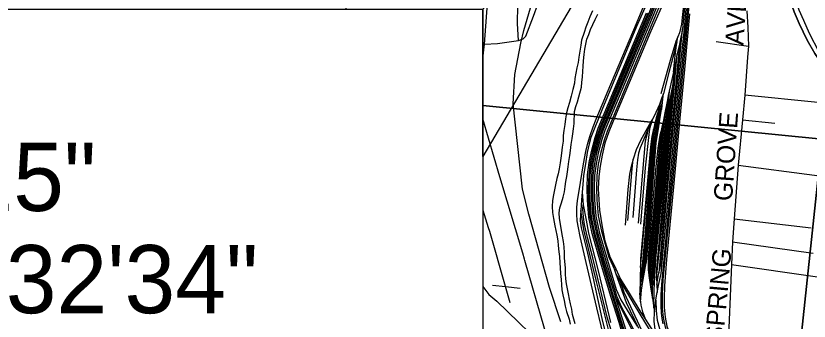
# Model space of a CAD drawing. Extents: x -8.2 to 38.5, y -0.1 to 21.9.
# Drawn here: x 4.076 to 5.706, y 16.75 to 17.376 of the extents above; entities that cross this region are included whole.
import ezdxf

# ---------------------------------------------------------------- set-up
doc = ezdxf.new("R2010")
doc.units = 0
for name, color, linetype in [('GM_X_Adjacent_County', 7, 'Continuous'), ('GM_X_Adjacent_County_Text', 7, 'Continuous'), ('GM_X_Airport_Location_Class_3', 7, 'Continuous'), ('GM_X_Major_Lake', 7, 'Continuous'), ('GM_X_Minor_River', 7, 'Continuous'), ('GM_X_State_Location', 7, 'Continuous'), ('GM_X_Township_Subdivision_Text', 7, 'Continuous'), ('GM_X_Township_Text', 7, 'Continuous'), ('GM_X_US_Location', 7, 'Continuous')]:
    doc.layers.add(name, color=color, linetype=linetype)

msp = doc.modelspace()

# ---------------------------------------------------------------- linework, layer by layer
at = {"layer": 'GM_X_Adjacent_County'}
for points in [[(5.0356, 17.3899), (5.4813, 17.8434), (5.0356, 17.0876)], [(2.2499, 17.3899), (5.0356, 17.3899), (5.0356, 16.67), (2.2499, 16.67)]]:
    msp.add_lwpolyline(points, close=True, dxfattribs=at)
at = {"layer": 'GM_X_Adjacent_County_Text'}
for points in [[(4.7544, 17.3899), (4.8395, 18.1926), (5.838, 18.0925), (5.7325, 17.1233), (5.0356, 17.1922)], [(5.0356, 17.1922), (5.7325, 17.1233), (5.6225, 16.0867), (4.6267, 16.1928), (4.6777, 16.67)]]:
    msp.add_lwpolyline(points, dxfattribs=at)
msp.add_lwpolyline([(5.7325, 17.1233), (6.7536, 16.9855), (6.65, 15.9814), (5.6225, 16.0867)], close=True, dxfattribs=at)
at = {"layer": 'GM_X_Airport_Location_Class_3'}
msp.add_lwpolyline([(5.6577, 17.4416), (5.6636, 17.4182), (5.675, 17.3847), (5.6851, 17.361), (5.7015, 17.3269), (5.7176, 17.2991), (5.74, 17.266), (5.7809, 17.2092), (5.8048, 17.1752), (5.8251, 17.1446), (5.8393, 17.1188), (5.8519, 17.0921), (5.8616, 17.0684)], dxfattribs=at)
at = {"layer": 'GM_X_Minor_River'}
for points in [[(5.2604, 17.3869), (5.2555, 17.3745), (5.2511, 17.3636), (5.247, 17.3534), (5.2433, 17.3425), (5.2383, 17.3267), (5.2365, 17.3161), (5.2346, 17.304), (5.2324, 17.2916), (5.2309, 17.2806), (5.2287, 17.27), (5.2265, 17.2587), (5.2247, 17.2481), (5.2236, 17.2383), (5.2202, 17.2251), (5.2168, 17.2115), (5.2131, 17.1987), (5.2101, 17.1877), (5.2075, 17.1772), (5.2053, 17.1651), (5.2038, 17.1537), (5.2016, 17.1409), (5.2005, 17.1307), (5.2002, 17.1189), (5.1987, 17.1068), (5.1969, 17.0943), (5.1954, 17.0845), (5.194, 17.0747), (5.1922, 17.0622), (5.19, 17.0524), (5.1874, 17.0426), (5.1848, 17.0297), (5.1826, 17.0195), (5.1804, 17.009), (5.1786, 16.9976), (5.1779, 16.9851), (5.1787, 16.9726), (5.1806, 16.9604), (5.1836, 16.9451), (5.1852, 16.9355), (5.1876, 16.926)], [(5.2033, 16.8899), (5.2025, 16.9024), (5.2009, 16.9131), (5.1989, 16.9238), (5.197, 16.936), (5.1947, 16.949), (5.1927, 16.9604), (5.1919, 16.9722), (5.1933, 16.982), (5.197, 16.9926), (5.2004, 17.0039), (5.203, 17.0148), (5.2048, 17.0261), (5.2062, 17.0363), (5.208, 17.0466), (5.2091, 17.0564), (5.2109, 17.0666), (5.2123, 17.0776), (5.2138, 17.0897), (5.2152, 17.1003), (5.2171, 17.1124), (5.2186, 17.1245), (5.22, 17.1343), (5.2214, 17.1445), (5.2232, 17.1555), (5.2239, 17.1798), (5.2265, 17.19), (5.2298, 17.1997), (5.2327, 17.2103), (5.2378, 17.2299), (5.2389, 17.2401), (5.2399, 17.2507), (5.241, 17.2628), (5.2413, 17.2727), (5.2424, 17.2841), (5.2439, 17.2969), (5.245, 17.3083), (5.2468, 17.3185), (5.2493, 17.3283), (5.253, 17.3381), (5.2567, 17.3482), (5.2612, 17.3587), (5.266, 17.3689), (5.2716, 17.3801)], [(5.1876, 16.926), (5.1895, 16.9145), (5.1904, 16.9046), (5.1916, 16.8921), (5.1928, 16.8826), (5.1936, 16.8696), (5.1944, 16.8593), (5.1949, 16.8476), (5.196, 16.8354), (5.1969, 16.8243), (5.1977, 16.8141), (5.1997, 16.8038), (5.2024, 16.7919), (5.2047, 16.7801), (5.2075, 16.7694), (5.2127, 16.7533), (5.215, 16.7431)], [(5.2249, 16.7442), (5.2222, 16.7538), (5.2198, 16.7633), (5.2182, 16.7744), (5.2155, 16.7851), (5.2135, 16.7947), (5.2115, 16.8057), (5.2095, 16.816), (5.2075, 16.826), (5.2059, 16.8362), (5.2054, 16.8461), (5.205, 16.8583), (5.2033, 16.8796), (5.2033, 16.8899)]]:
    msp.add_lwpolyline(points, dxfattribs=at)
at = {"layer": 'GM_X_State_Location'}
for points in [[(5.8616, 17.0684), (5.8519, 17.0921), (5.8393, 17.1188), (5.8251, 17.1446), (5.8048, 17.1752), (5.7809, 17.2092), (5.74, 17.266), (5.7176, 17.2991), (5.7015, 17.3269), (5.6851, 17.361), (5.675, 17.3847), (5.6636, 17.4182), (5.6577, 17.4416)], [(5.7332, 17.2923), (5.7268, 17.3018), (5.7066, 17.3406), (5.6952, 17.3667), (5.6853, 17.3884), (5.6739, 17.422), (5.6697, 17.4415)]]:
    msp.add_lwpolyline(points, dxfattribs=at)
at = {"layer": 'GM_X_Township_Subdivision_Text'}
for p, q in [((5.515, 17.3239), (5.5812, 17.3142)), ((5.5691, 17.1629), (5.6357, 17.1562)), ((5.5516, 16.9596), (5.7103, 16.9414)), ((5.5482, 16.9124), (5.7144, 16.8888)), ((5.5464, 16.8657), (5.7228, 16.8406))]:
    msp.add_line(p, q, dxfattribs=at)
for points in [[(5.1088, 17.3256), (5.1068, 17.361), (5.1072, 17.398), (5.1058, 17.467)], [(5.0385, 17.3182), (5.0653, 17.3195), (5.1088, 17.3256), (5.1181, 17.3291), (5.1239, 17.3351), (5.1395, 17.3756), (5.1485, 17.4003)], [(5.5603, 17.0702), (5.7167, 17.049), (5.7918, 17.039), (5.8252, 17.0351), (5.8501, 17.0361), (5.8658, 17.0381), (5.8712, 17.0388), (5.8842, 17.0417), (5.8948, 17.0443), (5.9018, 17.0467), (5.9202, 17.0556), (5.9463, 17.0717)], [(5.0917, 16.787), (5.0821, 16.8205), (5.0497, 16.9337), (5.0472, 16.9413), (5.036, 16.9766), (5.0356, 16.9772)], [(5.0555, 16.8233), (5.0821, 16.8205), (5.1122, 16.8173)]]:
    msp.add_lwpolyline(points, dxfattribs=at)
at = {"layer": 'GM_X_Township_Text'}
for points in [[(5.0356, 17.2886), (5.0385, 17.3182), (5.0465, 17.421), (5.0498, 17.4722), (5.0511, 17.4876), (5.0541, 17.532), (5.0635, 17.621), (5.0706, 17.6877), (5.073, 17.7051), (5.0765, 17.7221), (5.0958, 17.7745), (5.1025, 17.8577), (5.1157, 17.9389)], [(5.5776, 17.3866), (5.5802, 17.3524), (5.5812, 17.3142), (5.5794, 17.2916), (5.5738, 17.2134), (5.5691, 17.1629), (5.5603, 17.0702), (5.5516, 16.9596), (5.5482, 16.9124), (5.5464, 16.8657), (5.539, 16.6867)], [(5.733, 17.1975), (5.7237, 17.1984), (5.5738, 17.2134)], [(5.1208, 16.8768), (5.1172, 16.8892), (5.0703, 17.0456), (5.0356, 17.1653)], [(5.2379, 16.4752), (5.2159, 16.521), (5.2043, 16.5755), (5.1901, 16.6291), (5.176, 16.6824), (5.1622, 16.7341), (5.1216, 16.8739), (5.1208, 16.8768)], [(5.0356, 16.8218), (5.0375, 16.818), (5.0479, 16.8045), (5.0643, 16.7905), (5.176, 16.6824)]]:
    msp.add_lwpolyline(points, dxfattribs=at)
at = {"layer": 'GM_X_US_Location'}
for p, q in [((5.4343, 17.3219), (5.4359, 17.3331)), ((5.4395, 17.3186), (5.4349, 17.2983)), ((5.4304, 17.2778), (5.4268, 17.2608)), ((5.4271, 17.2426), (5.4304, 17.2778)), ((5.4268, 17.2608), (5.4184, 17.2215)), ((5.4256, 17.2329), (5.4271, 17.2426)), ((5.4068, 17.2172), (5.4028, 17.2068)), ((5.4047, 17.1995), (5.4068, 17.2172)), ((5.4141, 17.2004), (5.4095, 17.1776)), ((5.3992, 17.1635), (5.4028, 17.1845)), ((5.3814, 17.1604), (5.3766, 17.1487)), ((5.3837, 17.1646), (5.3814, 17.1604)), ((5.4048, 17.1541), (5.4008, 17.1386)), ((5.2398, 17.0145), (5.2417, 16.9885)), ((5.2959, 16.8838), (5.2958, 16.8843)), ((5.3749, 16.8554), (5.3771, 16.8376)), ((5.3095, 16.8461), (5.3065, 16.8545)), ((5.3162, 16.8349), (5.3095, 16.8461)), ((5.3923, 16.8382), (5.3928, 16.8249)), ((5.3928, 16.8249), (5.3935, 16.8081)), ((5.3829, 16.8027), (5.3838, 16.7965)), ((5.3838, 16.7965), (5.3869, 16.777)), ((5.3881, 16.7696), (5.391, 16.7929)), ((5.3869, 16.777), (5.3881, 16.7696)), ((5.3695, 16.7526), (5.4049, 16.6979))]:
    msp.add_line(p, q, dxfattribs=at)
for points in [[(5.4596, 16.6527), (5.4315, 16.6891), (5.4218, 16.7075), (5.4129, 16.7305), (5.4107, 16.7373), (5.4068, 16.757), (5.4045, 16.7761), (5.4045, 16.8043), (5.406, 16.8346), (5.4137, 16.9122), (5.4269, 17.0508), (5.4392, 17.1856), (5.4522, 17.3211), (5.4615, 17.4214), (5.4648, 17.4478), (5.4706, 17.47), (5.4805, 17.4998), (5.4888, 17.5218), (5.5077, 17.5612)], [(5.455, 17.4939), (5.4385, 17.4784), (5.4272, 17.4676), (5.4162, 17.457), (5.4025, 17.4445), (5.392, 17.4343), (5.3835, 17.4222), (5.3765, 17.4105), (5.3715, 17.4005), (5.3512, 17.3544), (5.2797, 17.183), (5.2575, 17.1264), (5.2536, 17.1138), (5.2496, 17.0958), (5.2463, 17.0728), (5.2422, 17.0485), (5.2411, 17.0302), (5.2398, 17.0145)], [(5.3935, 16.8081), (5.3965, 16.8226), (5.4017, 16.8475), (5.4061, 16.8937), (5.4175, 17.0103), (5.4249, 17.0946), (5.4416, 17.2729), (5.4488, 17.3427), (5.4542, 17.4061), (5.4569, 17.4283), (5.4691, 17.4747)], [(5.4683, 17.4862), (5.4626, 17.4734), (5.4556, 17.4465), (5.45, 17.418), (5.4454, 17.379), (5.4434, 17.3595), (5.4393, 17.3419), (5.4359, 17.3331)], [(5.4683, 17.4862), (5.4641, 17.4722), (5.4552, 17.4322), (5.4505, 17.4019), (5.4456, 17.3494)], [(5.4266, 17.4486), (5.4259, 17.4479), (5.4001, 17.4227), (5.3916, 17.4106), (5.3836, 17.3991), (5.3764, 17.3812), (5.3229, 17.2534), (5.2771, 17.1444), (5.2707, 17.1253), (5.2632, 17.0968), (5.2585, 17.0743), (5.2554, 17.0494), (5.2546, 17.0223), (5.2553, 16.9983), (5.258, 16.9634), (5.2651, 16.9308), (5.282, 16.8718), (5.304, 16.7997), (5.3211, 16.7453), (5.3415, 16.6791), (5.3483, 16.6605)], [(5.4229, 17.4406), (5.4025, 17.4207), (5.3942, 17.4088), (5.3863, 17.3976), (5.3793, 17.38), (5.3258, 17.2522), (5.28, 17.1433), (5.2736, 17.1244), (5.2662, 17.0961), (5.2616, 17.0738), (5.2585, 17.0492), (5.2577, 17.0223), (5.2584, 16.9984), (5.2611, 16.9639), (5.2682, 16.9316), (5.285, 16.8727), (5.307, 16.8006)], [(5.4192, 17.4326), (5.4048, 17.4187), (5.3967, 17.4071), (5.3891, 17.3961), (5.3821, 17.3788), (5.3287, 17.251), (5.2829, 17.1422), (5.2766, 17.1235), (5.2692, 17.0954), (5.2646, 17.0733), (5.2616, 17.0489), (5.2608, 17.0223), (5.2615, 16.9986), (5.2642, 16.9643), (5.2712, 16.9324), (5.288, 16.8736), (5.31, 16.8015), (5.32, 16.7784), (5.3363, 16.7493), (5.3724, 16.6799), (5.377, 16.6703)], [(5.1958, 16.748), (5.1721, 16.8188), (5.1299, 16.9692), (5.1168, 17.0207), (5.1069, 17.1142), (5.0979, 17.1958), (5.1008, 17.2564), (5.1131, 17.3203), (5.1196, 17.3464), (5.1401, 17.417)], [(5.4151, 17.4239), (5.4075, 17.4165), (5.3995, 17.4051), (5.3921, 17.3945), (5.3853, 17.3775), (5.3318, 17.2497), (5.2861, 17.141), (5.2799, 17.1225), (5.2726, 17.0946), (5.268, 17.0727), (5.265, 17.0487), (5.2642, 17.0223), (5.2649, 16.9988), (5.2676, 16.9648), (5.2745, 16.9332), (5.2913, 16.8746), (5.3096, 16.8144), (5.3188, 16.7932), (5.3318, 16.7721), (5.3461, 16.7488), (5.3526, 16.7394)], [(5.4126, 17.4182), (5.4034, 17.4024), (5.3962, 17.3922), (5.3896, 17.3757), (5.3361, 17.2479), (5.2905, 17.1393), (5.2844, 17.1212), (5.2771, 17.0936), (5.2726, 17.072), (5.2697, 17.0483), (5.2689, 17.0223), (5.2695, 16.999), (5.2722, 16.9655), (5.279, 16.9343), (5.2943, 16.8808), (5.3065, 16.8545)], [(5.4126, 17.4182), (5.3803, 17.3448), (5.3094, 17.1755), (5.294, 17.1381), (5.2863, 17.1152), (5.2803, 17.0903), (5.2762, 17.068), (5.2736, 17.0463), (5.2723, 17.0214), (5.275, 16.9775), (5.2803, 16.943), (5.286, 16.9148), (5.2958, 16.8843)], [(5.2871, 16.7029), (5.2694, 16.7766), (5.2477, 16.8702), (5.2354, 16.9237), (5.2316, 16.9411), (5.2293, 16.9556), (5.2284, 16.9693), (5.2288, 16.9835), (5.2301, 16.9965), (5.2357, 17.0343), (5.2424, 17.0728), (5.2469, 17.0976), (5.2513, 17.1148), (5.2559, 17.1307), (5.2624, 17.1486), (5.2685, 17.1644), (5.293, 17.2229), (5.3511, 17.3608), (5.3659, 17.3969)], [(5.4059, 16.7439), (5.4038, 16.7551), (5.4025, 16.7669), (5.4015, 16.7801), (5.4015, 16.8036), (5.4029, 16.8247), (5.4267, 17.0755), (5.4387, 17.2092), (5.4579, 17.408)], [(5.513, 16.1303), (5.5058, 16.139), (5.498, 16.1502), (5.4929, 16.1617), (5.4614, 16.2648), (5.4231, 16.3912), (5.3816, 16.5275), (5.3427, 16.6542), (5.3253, 16.7133), (5.3152, 16.7468), (5.2993, 16.7983), (5.2772, 16.8704), (5.2603, 16.9296), (5.2531, 16.9627), (5.2503, 16.998), (5.2496, 17.0223), (5.2505, 17.0498), (5.2536, 17.0751), (5.2583, 17.098), (5.2659, 17.1267), (5.2725, 17.1461), (5.3184, 17.2553), (5.3718, 17.383)], [(5.3741, 17.3821), (5.3206, 17.2543), (5.2748, 17.1453), (5.2683, 17.126), (5.2608, 17.0974), (5.256, 17.0747), (5.2529, 17.0496), (5.2521, 17.0223), (5.2528, 16.9981), (5.2555, 16.963), (5.2627, 16.9302), (5.2796, 16.8711), (5.3017, 16.799), (5.3205, 16.7389), (5.3346, 16.6895), (5.3491, 16.6445), (5.3619, 16.6019), (5.4018, 16.4686), (5.4374, 16.353), (5.4719, 16.2387), (5.4859, 16.1925), (5.4942, 16.1639), (5.502, 16.1493), (5.5074, 16.14)], [(5.4601, 17.3807), (5.45, 17.2666), (5.4402, 17.1665), (5.427, 17.0256), (5.413, 16.8759), (5.4084, 16.8221), (5.4078, 16.7961), (5.4083, 16.7779), (5.4101, 16.7578), (5.4137, 16.7389), (5.4214, 16.7166), (5.4306, 16.697), (5.4479, 16.6699), (5.4735, 16.6322), (5.5061, 16.5883), (5.5357, 16.5464), (5.549, 16.5275), (5.5653, 16.4997), (5.5746, 16.4815), (5.5858, 16.4606)], [(5.3971, 16.8479), (5.4002, 16.8633), (5.4034, 16.8949), (5.4338, 17.2253), (5.4456, 17.3494)], [(5.4456, 17.3494), (5.4404, 17.3228), (5.4395, 17.3186)], [(5.4359, 17.3331), (5.4322, 17.3235), (5.4202, 17.2847), (5.4104, 17.2506), (5.4013, 17.2161)], [(5.4395, 17.3186), (5.4241, 17.155), (5.3992, 16.8727), (5.3971, 16.8479)], [(5.4343, 17.3219), (5.4173, 17.2599), (5.4068, 17.2172)], [(5.4268, 17.2608), (5.4306, 17.295), (5.4343, 17.3219)], [(5.3923, 16.8382), (5.4033, 16.9426), (5.4153, 17.0801), (5.4349, 17.2983)], [(5.4349, 17.2983), (5.4325, 17.2875), (5.4304, 17.2778)], [(5.3848, 16.8243), (5.3882, 16.8671), (5.419, 17.1976), (5.4256, 17.2329)], [(5.3869, 16.777), (5.3871, 16.813), (5.3886, 16.8406), (5.3911, 16.8776), (5.3931, 16.8979), (5.4037, 17.0071), (5.4214, 17.1987), (5.4241, 17.2239), (5.4256, 17.2329)], [(5.4271, 17.2426), (5.4014, 16.9543), (5.3923, 16.8577), (5.3921, 16.8438), (5.3923, 16.8382)], [(5.4184, 17.2215), (5.4157, 17.19), (5.4061, 17.0894), (5.3843, 16.8489), (5.3848, 16.8243)], [(5.4184, 17.2215), (5.4172, 17.2162), (5.4141, 17.2004)], [(5.3582, 16.8037), (5.3696, 16.9317), (5.3846, 17.1193), (5.3888, 17.1458), (5.3944, 17.1649), (5.4047, 17.1995)], [(5.4141, 17.2004), (5.4132, 17.1903), (5.4037, 17.0897), (5.3818, 16.849), (5.3824, 16.8243), (5.3829, 16.8027)], [(5.4028, 17.2068), (5.3981, 17.1946), (5.3871, 17.1706), (5.3837, 17.1646)], [(5.4028, 17.2068), (5.3968, 17.1851), (5.3918, 17.1669), (5.3881, 17.1526), (5.3858, 17.1432)], [(5.4028, 17.1845), (5.4029, 17.1848), (5.4047, 17.1995)], [(5.3626, 16.8222), (5.365, 16.85), (5.3721, 16.9315), (5.3871, 17.119), (5.3912, 17.1452), (5.3968, 17.1642), (5.4028, 17.1845)], [(5.4095, 17.1776), (5.4012, 17.0899), (5.3793, 16.8491), (5.3799, 16.8242)], [(5.4095, 17.1776), (5.4049, 17.1546), (5.4048, 17.1541)], [(5.3766, 17.1487), (5.37, 17.1328), (5.3585, 17.1054), (5.3555, 17.0942), (5.3534, 17.0805), (5.3512, 17.0602), (5.3437, 16.9622)], [(5.3814, 17.1604), (5.377, 17.1526), (5.3591, 17.1205), (5.3502, 17.1011), (5.3445, 17.082)], [(5.3553, 16.951), (5.3698, 17.1195), (5.3736, 17.1355), (5.3766, 17.1487)], [(5.3837, 17.1646), (5.378, 17.1447), (5.3764, 17.133), (5.3692, 17.0646), (5.3591, 16.9484)], [(5.3675, 16.8498), (5.3746, 16.9313), (5.3895, 17.1187), (5.3936, 17.1447), (5.3992, 17.1635)], [(5.3675, 16.8498), (5.3696, 16.8616), (5.3715, 16.8711), (5.3764, 16.9245), (5.3886, 17.0802), (5.3917, 17.1159), (5.3958, 17.1401), (5.3983, 17.158), (5.3992, 17.1635)], [(5.4048, 17.1541), (5.3987, 17.0901), (5.3768, 16.8492), (5.3771, 16.8376)], [(5.3858, 17.1432), (5.3853, 17.1409), (5.3828, 17.1285), (5.38, 17.1075), (5.3596, 16.8773), (5.3593, 16.866), (5.3595, 16.8596)], [(5.3595, 16.8596), (5.3747, 17.023), (5.3858, 17.1432)], [(5.4008, 17.1386), (5.399, 17.1314), (5.395, 17.1048), (5.3908, 17.0673), (5.3825, 16.9753), (5.3753, 16.8806), (5.3748, 16.8559), (5.3749, 16.8554)], [(5.4008, 17.1386), (5.3962, 17.0903), (5.3749, 16.8554)], [(5.3445, 17.082), (5.3394, 17.0643), (5.3369, 17.0516), (5.3333, 17.0199), (5.3277, 16.9464)], [(5.3331, 16.9559), (5.3424, 17.0621), (5.3445, 17.082)], [(5.2398, 17.0145), (5.2384, 16.9985), (5.2369, 16.9765)], [(5.3101, 16.6957), (5.2993, 16.7313), (5.2911, 16.7578), (5.2613, 16.8798), (5.2506, 16.9212), (5.2444, 16.9482), (5.2424, 16.963), (5.2409, 16.9804), (5.2417, 16.9885)], [(5.2417, 16.9885), (5.2475, 16.9567), (5.2526, 16.9304), (5.272, 16.8527), (5.2947, 16.7586), (5.2975, 16.7466)], [(5.2369, 16.9765), (5.2363, 16.9686), (5.2355, 16.9556), (5.2371, 16.9413), (5.2506, 16.8888), (5.2593, 16.85), (5.2801, 16.7553), (5.2868, 16.7269)], [(5.2948, 16.7269), (5.2873, 16.7569), (5.2687, 16.831), (5.2439, 16.9342), (5.2401, 16.9543), (5.2369, 16.9765)], [(5.3065, 16.8545), (5.2959, 16.8838), (5.305, 16.8644), (5.3182, 16.8357), (5.3361, 16.8073), (5.3598, 16.7676), (5.3695, 16.7526)], [(5.3595, 16.8596), (5.3596, 16.8578), (5.3588, 16.843), (5.3585, 16.8288), (5.358, 16.8132), (5.3582, 16.8037)], [(5.3561, 16.7341), (5.3308, 16.7869), (5.3095, 16.8461)], [(5.3626, 16.8222), (5.3649, 16.8354), (5.3675, 16.8498)], [(5.3928, 16.8249), (5.3965, 16.8453), (5.3971, 16.8479)], [(5.4042, 16.6888), (5.3989, 16.6973), (5.3471, 16.7828), (5.333, 16.8065), (5.3233, 16.8231), (5.3162, 16.8349)], [(5.3162, 16.8349), (5.3254, 16.8091), (5.3391, 16.7798), (5.366, 16.7207), (5.3739, 16.7029)], [(5.3771, 16.8376), (5.3775, 16.834), (5.3815, 16.8113), (5.3829, 16.8027)], [(5.3838, 16.7965), (5.3843, 16.8172), (5.3848, 16.8243)], [(5.3591, 16.7891), (5.3611, 16.8134), (5.3626, 16.8222)], [(5.391, 16.7929), (5.3921, 16.8014), (5.3935, 16.8081)], [(5.3825, 16.6533), (5.3703, 16.6787), (5.3519, 16.7124), (5.3187, 16.7773), (5.307, 16.8006)], [(5.3415, 16.7035), (5.335, 16.7182), (5.3292, 16.7325), (5.3228, 16.7521), (5.3136, 16.7815), (5.307, 16.8006)], [(5.3582, 16.8037), (5.3583, 16.7966), (5.3591, 16.7891)], [(5.391, 16.7929), (5.3915, 16.771), (5.3936, 16.7516), (5.3984, 16.7346), (5.4047, 16.7207), (5.4152, 16.7031), (5.4344, 16.672), (5.4538, 16.6419), (5.4724, 16.6179), (5.4774, 16.6114)], [(5.3591, 16.7891), (5.3598, 16.7823), (5.3632, 16.7685), (5.3695, 16.7526)], [(5.4049, 16.6979), (5.3973, 16.7124), (5.3903, 16.7274), (5.3876, 16.7489), (5.3881, 16.7696)]]:
    msp.add_lwpolyline(points, dxfattribs=at)

# ---------------------------------------------------------------- texts
at = {"layer": 'GM_X_Adjacent_County'}
for s, p in [('LATITUDE:  N39°9\'15" ', (2.3471, 16.9758)), ('LONGITUDE:  W84°32\'34"', (2.3471, 16.7658))]:
    msp.add_text(s, height=0.14, dxfattribs=at).set_placement(p)
at = {"layer": 'GM_X_Major_Lake'}
for s, rotation, p in [('AVE', 86.0569, (5.5708, 17.3152)), ('GROVE', 86.055, (5.5474, 16.9952)), ('SPRING', 84.7927, (5.5288, 16.7042))]:
    msp.add_text(s, height=0.03788, rotation=rotation, dxfattribs=at).set_placement(p)

doc.saveas('drawing.dxf')
